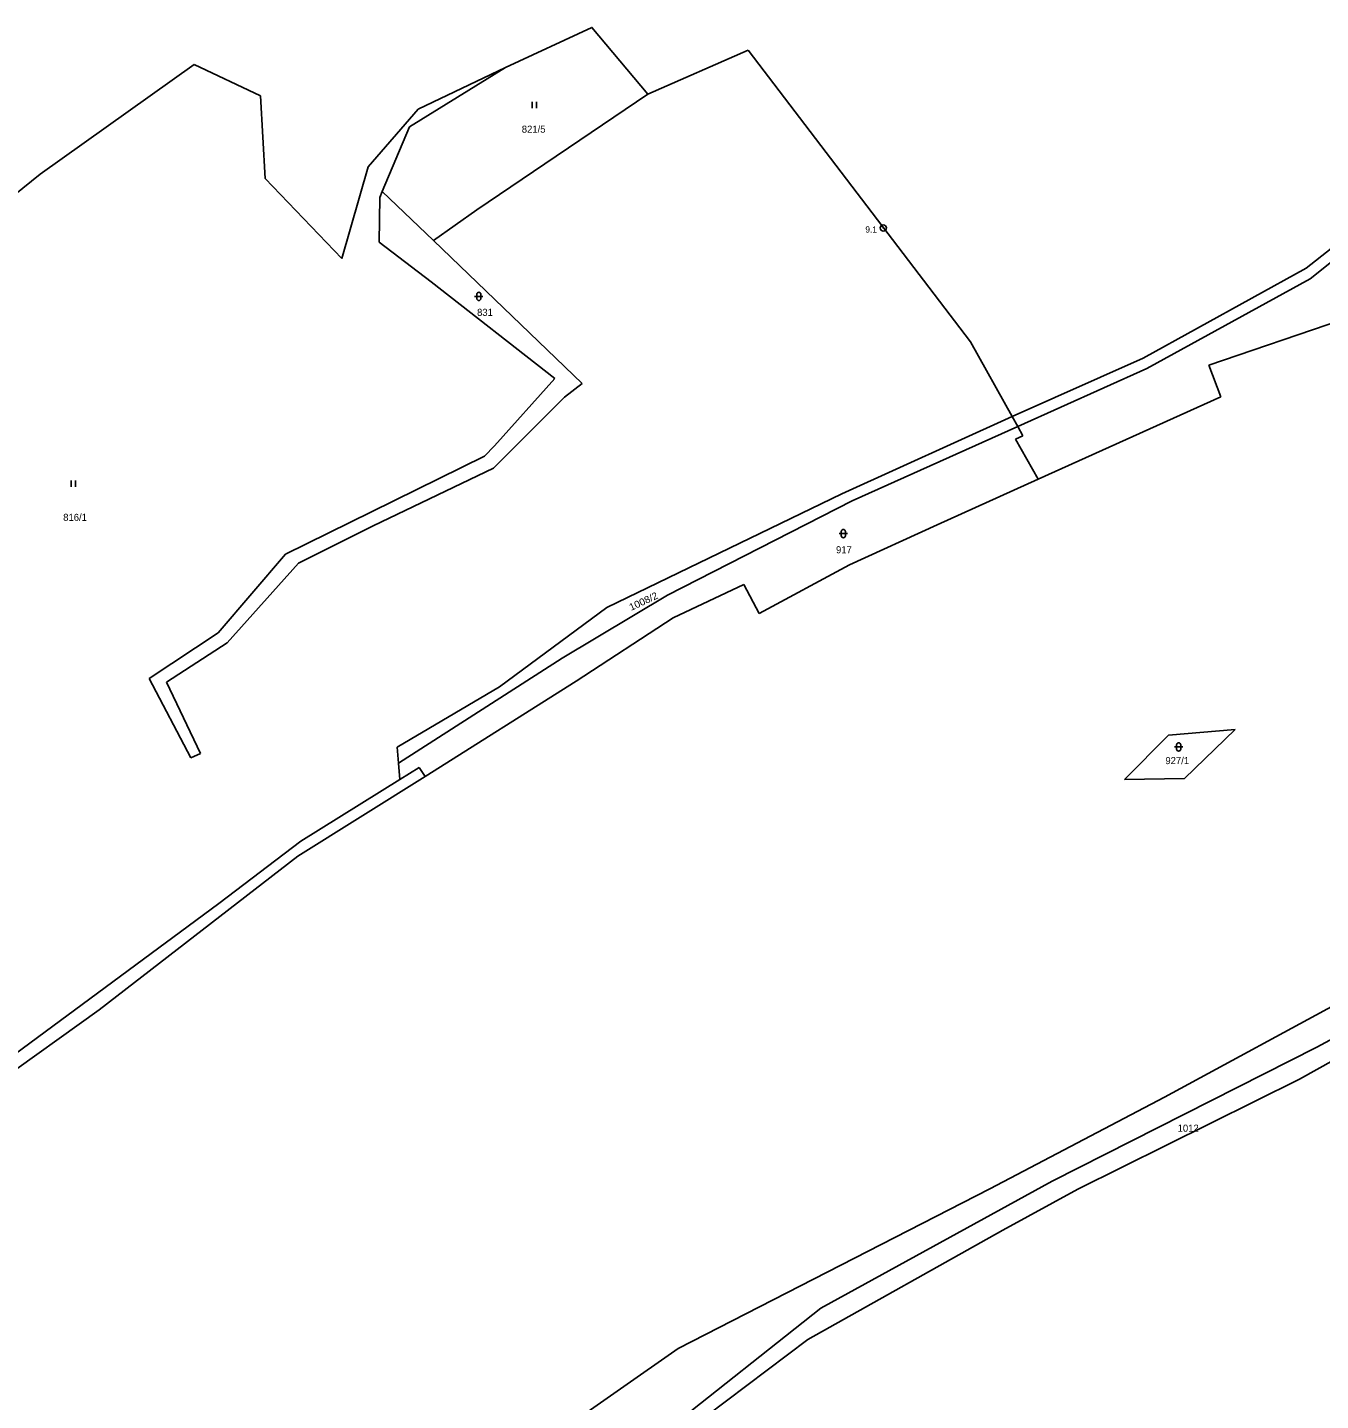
# Model space of a CAD drawing. Extents: x -744132 to -742433, y -984679 to -982287.
# Drawn here: x -743750.5 to -743440.4, y -983360 to -983030.7 of the extents above; entities that cross this region are included whole.
import ezdxf
from ezdxf.enums import TextEntityAlignment as Align

# ---------------------------------------------------------------- set-up
doc = ezdxf.new("R2010")
doc.units = 0
doc.header["$LTSCALE"] = 0.68
for name, color, linetype, lineweight in [('1', 7, 'Continuous', 25), ('3', 7, 'Continuous', 25), ('8', 7, 'Continuous', 25)]:
    doc.layers.add(name, color=color, linetype=linetype, lineweight=lineweight)
doc.layers.add('2', color=7, linetype='Continuous')

msp = doc.modelspace()

# ---------------------------------------------------------------- linework, layer by layer
at = {"layer": '1'}
for p, q in [((-743601.7, -983046.71), (-743577.65, -983036.2)), ((-743577.65, -983036.2), (-743524.36, -983106.12)), ((-743710.48, -983039.62), (-743747.4, -983065.95)), ((-743694.58, -983047.14), (-743710.48, -983039.62)), ((-743658.86, -983054.57), (-743635.86, -983040.32)), ((-743656.74, -983050.33), (-743635.86, -983040.32)), ((-743694.58, -983047.14), (-743693.43, -983066.95)), ((-743601.7, -983046.71), (-743642.68, -983074.43)), ((-743668.75, -983064.17), (-743656.74, -983050.33)), ((-743665.42, -983070.09), (-743658.86, -983054.57)), ((-743675.1, -983086.12), (-743668.75, -983064.17)), ((-743747.4, -983065.95), (-743775.33, -983088.23)), ((-743693.43, -983066.95), (-743675.1, -983086.12)), ((-743666.09, -983082.26), (-743665.97, -983071.5)), ((-743665.97, -983071.5), (-743665.42, -983070.09)), ((-743665.42, -983070.09), (-743653.1, -983081.79)), ((-743642.68, -983074.43), (-743653.1, -983081.79)), ((-743443.8, -983088.48), (-743428.78, -983076.59)), ((-743442.87, -983090.98), (-743426.84, -983078.17)), ((-743653.65, -983091.75), (-743666.09, -983082.26)), ((-743653.1, -983081.79), (-743617.45, -983116.12)), ((-743482.93, -983110.04), (-743443.8, -983088.48)), ((-743623.99, -983114.95), (-743653.65, -983091.75)), ((-743482.06, -983112.52), (-743442.87, -983090.98)), ((-743467.2, -983111.76), (-743435.24, -983100.86)), ((-743524.36, -983106.12), (-743514.34, -983124.04)), ((-743514.34, -983124.04), (-743482.93, -983110.04)), ((-743464.27, -983119.31), (-743467.2, -983111.76)), ((-743638.5, -983131.09), (-743623.99, -983114.95)), ((-743512.99, -983126.4), (-743482.06, -983112.52)), ((-743617.45, -983116.12), (-743621.68, -983119.4)), ((-743621.68, -983119.4), (-743635.73, -983133.47)), ((-743508.13, -983139.1), (-743464.27, -983119.31)), ((-743555.14, -983142.57), (-743514.34, -983124.04)), ((-743514.34, -983124.04), (-743512.99, -983126.4)), ((-743552.71, -983144.27), (-743512.99, -983126.4)), ((-743512.99, -983126.4), (-743511.81, -983128.67)), ((-743640.86, -983133.53), (-743638.5, -983131.09)), ((-743513.53, -983129.43), (-743511.81, -983128.67)), ((-743513.53, -983129.43), (-743508.13, -983139.1)), ((-743667.95, -983146.86), (-743640.86, -983133.53)), ((-743635.73, -983133.47), (-743638.72, -983136.45)), ((-743638.72, -983136.45), (-743667.58, -983150.27)), ((-743508.13, -983139.1), (-743532.31, -983150.02)), ((-743611.56, -983169.87), (-743555.14, -983142.57)), ((-743596.96, -983166.89), (-743552.71, -983144.27)), ((-743688.63, -983157.07), (-743667.95, -983146.86)), ((-743667.58, -983150.27), (-743685.46, -983159.21)), ((-743553.37, -983159.63), (-743532.31, -983150.02)), ((-743704.71, -983175.94), (-743688.63, -983157.07)), ((-743685.46, -983159.21), (-743702.56, -983178.3)), ((-743575, -983171.28), (-743553.37, -983159.63)), ((-743595.64, -983172.3), (-743578.66, -983164.35)), ((-743578.66, -983164.35), (-743575, -983171.28)), ((-743622.27, -983181.97), (-743596.96, -983166.89)), ((-743637.29, -983188.9), (-743611.56, -983169.87)), ((-743618.88, -983187.5), (-743595.64, -983172.3)), ((-743721.27, -983186.9), (-743704.71, -983175.94)), ((-743702.56, -983178.3), (-743717.14, -983187.77)), ((-743661.51, -983207.16), (-743622.27, -983181.97)), ((-743711.28, -983205.9), (-743721.27, -983186.9)), ((-743655.06, -983210.37), (-743618.88, -983187.5)), ((-743717.14, -983187.77), (-743708.94, -983204.82)), ((-743661.83, -983203.37), (-743637.29, -983188.9)), ((-743476.83, -983200.45), (-743487.41, -983211.09)), ((-743460.82, -983199.1), (-743476.83, -983200.45)), ((-743472.97, -983210.88), (-743460.82, -983199.1)), ((-743661.83, -983203.37), (-743661.51, -983207.16)), ((-743708.94, -983204.82), (-743711.28, -983205.9)), ((-743661.51, -983207.16), (-743661.17, -983211.11)), ((-743685.62, -983229.51), (-743655.06, -983210.37)), ((-743656.52, -983208.23), (-743661.17, -983211.11)), ((-743655.06, -983210.37), (-743656.52, -983208.23)), ((-743661.17, -983211.11), (-743684.94, -983225.84)), ((-743487.41, -983211.09), (-743472.97, -983210.88)), ((-743441.23, -983275.3), (-743339.3, -983219.21)), ((-743337.2, -983222.45), (-743445.44, -983282.95)), ((-743684.94, -983225.84), (-743704.56, -983240.84)), ((-743733.29, -983266.29), (-743685.62, -983229.51)), ((-743704.56, -983240.84), (-743753.54, -983277.08)), ((-743477.78, -983287.24), (-743430.41, -983261.53)), ((-743765.21, -983289.16), (-743733.29, -983266.29)), ((-743504.73, -983307.38), (-743441.23, -983275.3)), ((-743445.44, -983282.95), (-743498.59, -983309.31)), ((-743519.66, -983309.25), (-743477.78, -983287.24)), ((-743594.46, -983347.58), (-743519.66, -983309.25)), ((-743560.21, -983337.88), (-743504.73, -983307.38)), ((-743498.59, -983309.31), (-743516.6, -983319.16)), ((-743516.6, -983319.16), (-743563.34, -983345.36)), ((-743614.1, -983380.55), (-743560.21, -983337.88)), ((-743563.34, -983345.36), (-743615.25, -983384.5)), ((-743657.43, -983391.5), (-743594.46, -983347.58))]:
    msp.add_line(p, q, dxfattribs=at)
msp.add_lwpolyline([(-743635.86, -983040.32), (-743615.09, -983030.73), (-743601.7, -983046.71)], dxfattribs=at)
at = {"layer": '3'}
for p, q in [((-743629.421, -983050.07), (-743629.421, -983048.57)), ((-743628.42, -983050.07), (-743628.42, -983048.57)), ((-743643.231, -983095.221), (-743641.229, -983095.221)), ((-743642.731, -983094.721), (-743642.731, -983095.722)), ((-743641.729, -983095.722), (-743641.729, -983094.721)), ((-743739.981, -983140.86), (-743739.981, -983139.36)), ((-743738.98, -983140.86), (-743738.98, -983139.36)), ((-743555.801, -983152.111), (-743553.799, -983152.111)), ((-743555.301, -983151.611), (-743555.301, -983152.612)), ((-743554.299, -983152.612), (-743554.299, -983151.611)), ((-743475.421, -983203.281), (-743473.419, -983203.281)), ((-743474.921, -983202.781), (-743474.921, -983203.782)), ((-743473.919, -983203.782), (-743473.919, -983202.781))]:
    msp.add_line(p, q, dxfattribs=at)
for centre, start, end in [((-743642.23, -983094.7209), 0, 180), ((-743642.23, -983095.7209), 180, 359.98789), ((-743554.8, -983151.6109), 0, 180), ((-743554.8, -983152.6109), 180, 359.98789), ((-743474.42, -983202.7809), 0, 180), ((-743474.42, -983203.7809), 180, 359.98789)]:
    msp.add_arc(centre, 0.5, start, end, dxfattribs=at)
at = {"layer": '8'}
for radius in [0.75, 0.03]:
    msp.add_circle((-743545.25, -983078.8198), radius, dxfattribs=at)

# ---------------------------------------------------------------- texts
at = {"layer": '2'}
for s, p in [('821/5', (-743631.93, -983055.975)), ('831', (-743642.65, -983099.905)), ('816/1', (-743741.9, -983149.065)), ('917', (-743556.57, -983156.835)), ('927/1', (-743477.59, -983207.405)), ('1012', (-743474.65, -983295.555))]:
    msp.add_text(s, height=1.7, dxfattribs=at).set_placement(p)
at = {"layer": '2', "width": 1.05}
msp.add_text('1008/2', height=1.7, rotation=25, dxfattribs=at).set_placement((-743605.7, -983170.665))
at = {"layer": '8'}
msp.add_text('9.1', height=1.5, dxfattribs=at).set_placement((-743546.75, -983079.937), align=Align.RIGHT)

doc.saveas('drawing.dxf')
